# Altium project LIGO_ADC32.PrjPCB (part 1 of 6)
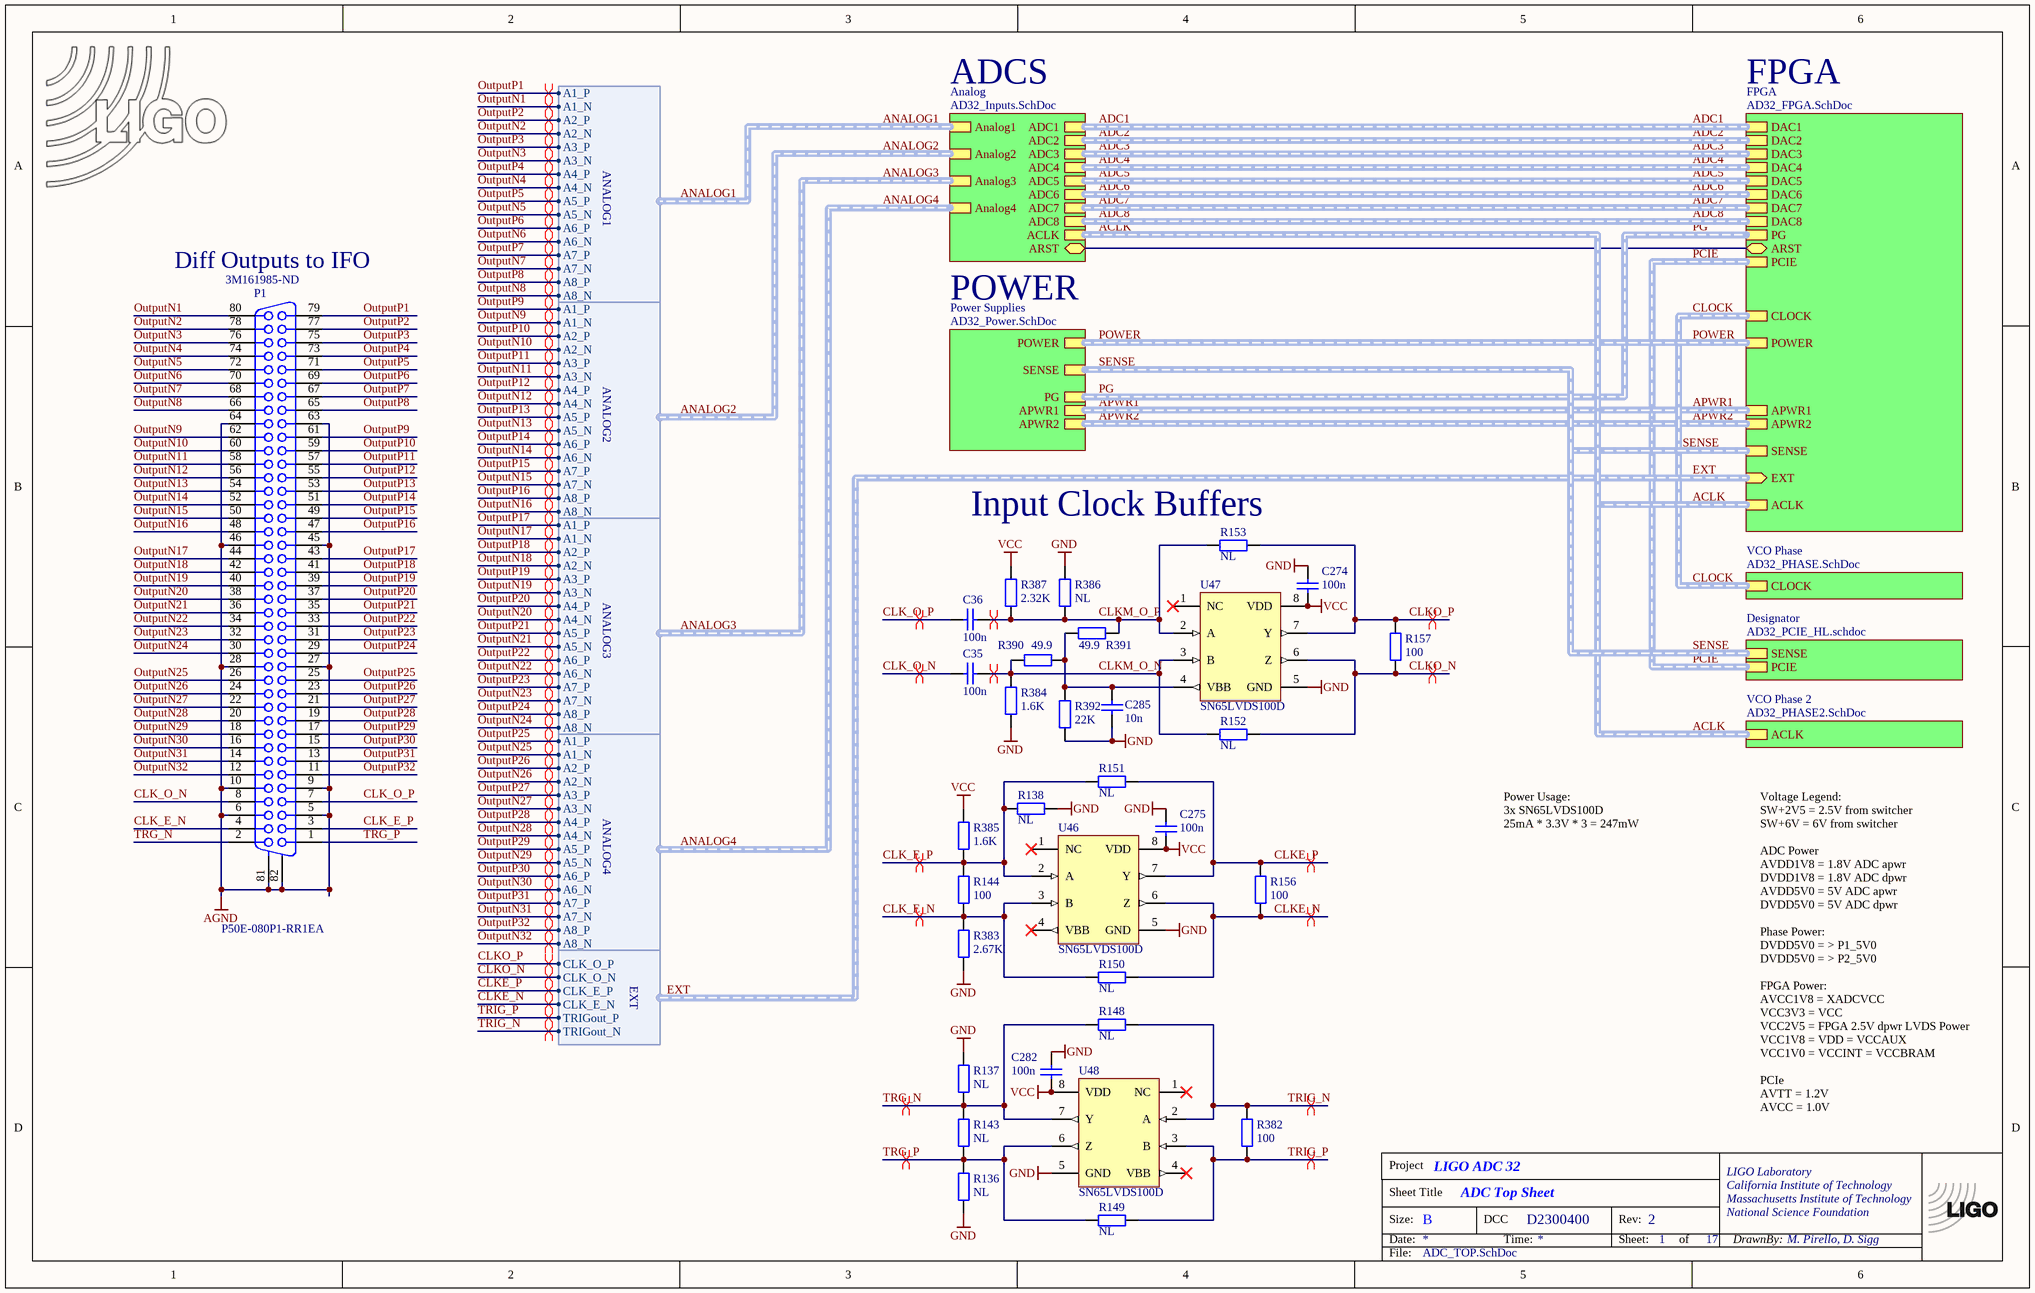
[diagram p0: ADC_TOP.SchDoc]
DCC: D2300400; DCCRevision: 1; ENG: M. Pirello, D. Sigg; Project: LIGO ADC 32; REV: 2; SHEETSIZE: B
17 sheets, 1409 parts. Net scope: hierarchical (ports join the sheet entries above them; power ports are global).
Board file: AD32.PcbDoc
Sheets:
  ADC_TOP.SchDoc
    Analog = AD32_Inputs.SchDoc
      ADC1 = AD32_Conv.SchDoc
        FrontEnd = AdcDaughterFrontEnd.SchDoc
      ADC2 = AD32_Conv.SchDoc
        FrontEnd = AdcDaughterFrontEnd.SchDoc
      ADC3 = AD32_Conv.SchDoc
        FrontEnd = AdcDaughterFrontEnd.SchDoc
      ADC4 = AD32_Conv.SchDoc
        FrontEnd = AdcDaughterFrontEnd.SchDoc
      ADC5 = AD32_Conv.SchDoc
        FrontEnd = AdcDaughterFrontEnd.SchDoc
      ADC6 = AD32_Conv.SchDoc
        FrontEnd = AdcDaughterFrontEnd.SchDoc
      ADC7 = AD32_Conv.SchDoc
        FrontEnd = AdcDaughterFrontEnd.SchDoc
      ADC8 = AD32_Conv.SchDoc
        FrontEnd = AdcDaughterFrontEnd.SchDoc
    FPGA = AD32_FPGA.SchDoc
      FPGA INTERFACE = FPGA_ARTIX7.SchDoc
      ADC = AD32_XADC.SchDoc
      PRG = AD32_FLASH.SchDoc
    VCO Phase = AD32_PHASE.SchDoc
    Designator = AD32_PCIE_HL.SchDoc
      ChassisTimingInterfacePCIE = AD32_PCIE.SchDoc
    Power Supplies = AD32_Power.SchDoc
      Diff Power = AD32_Bipolar1.SchDoc
      Linear Supplies = AD32_Linear1.SchDoc
      Pos Power = AD32_Bipolar2.SchDoc
      PowerFPGA = AD32_PowerFPGA.SchDoc
    VCO Phase 2 = AD32_PHASE2.SchDoc

## Sheet ADC_TOP.SchDoc: ADC Top Sheet
size B; Engineer: Daniel Sigg; Revision: 1; SheetNumber: 1; SheetTotal: 17; PageSetup: Record=PageOptions¦CenterHorizontal=True¦CenterVertical=True¦PrintScale=1.12¦XCorrection=1.00¦YCorrection=1.00¦PrintKind=0¦BorderSize=5000000¦LeftOffset=0¦BottomOffset=0¦Orientation=2¦PaperLength=1000¦PaperWidth=1000¦Scale=100¦PaperSource=7¦PrintQuality=-4¦MediaType=1¦DitherType=10¦PaperKind=Letter¦PrintScaleMode=1

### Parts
(Parts that share a designator on the sheet are numbered #1, #2 ... from top to bottom, then left to right.)
*?#1  TitleBlock  (value not drawn)  (graphical)
C35  100n  [CC1005-0402]
C36  100n  [CC1005-0402]
C274  100n  [CC1005-0402]
C275  100n  [CC1005-0402]
C282  100n  [CC1005-0402]
C285  10n  [CC1005-0402]
LOGO1  LIGO logo  [LIGO-LOGO-SM]  (value not drawn)  (no BOM)
P1  P50E-080P1-RR1EA  Supplier Part Number 1: 3M161985-ND  [P50E-080-SR1]
R136  NL  [CR1005-0402]
R137  NL  [CR1005-0402]
R138  NL  [CR1005-0402]
R143  NL  [CR1005-0402]
R144  100  [CR1005-0402]
R148  NL  [CR1005-0402]
R149  NL  [CR1005-0402]
R150  NL  [CR1005-0402]
R151  NL  [CR1005-0402]
R152  NL  [CR1005-0402]
R153  NL  [CR1005-0402]
R156  100  [CR0603-0201]
R157  100  [CR0603-0201]
R382  100  [CR0603-0201]
R383  2.67K  [CR1005-0402]
R384  1.6K  [CR1005-0402]
R385  1.6K  [CR1005-0402]
R386  NL  [CR1005-0402]
R387  2.32K  [CR1005-0402]
R390  49.9  [CR1005-0402]
R391  49.9  [CR1005-0402]
R392  22K  [CR1005-0402]
U46  SN65LVDS100D  [MSOP8]
U47  SN65LVDS100D  [MSOP8]
U48  SN65LVDS100D  [MSOP8]

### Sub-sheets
Analog = AD32_Inputs.SchDoc: Analog1 (harness ANALOG1), Analog2 (harness ANALOG2), Analog3 (harness ANALOG3), Analog4 (harness ANALOG4), ADC1 (harness DAC1), ADC2 (harness DAC2), ADC3 (harness DAC3), ADC4 (harness DAC4), ADC5 (harness DAC4), ADC6 (harness DAC4), ADC8 (harness DAC4), ADC7 (harness DAC4), ACLK (harness DAC4), ARST (bidir)
Designator = AD32_PCIE_HL.schdoc: PCIE (harness PCIE), SENSE (harness SENSE)
FPGA = AD32_FPGA.SchDoc: DAC4 (harness S1_16), DAC3 (harness S17_32), DAC2 (harness S33_48), DAC7 (harness S49_64), CLOCK (harness CLOCK), PCIE (harness PCIE), POWER (harness POWER), APWR1 (harness CONFIG), APWR2 (harness CONFIG), PG (harness APWR2), SENSE (harness SENSE), EXT (in, harness EXT), DAC5 (harness S49_64), DAC6 (harness S49_64), DAC8 (harness S49_64), DAC1 (harness S49_64), ACLK (harness CLOCK), ARST (bidir)
Power Supplies = AD32_Power.SchDoc: PG (harness APWR2), SENSE (harness SENSE), APWR1 (harness APWR2), APWR2 (harness APWR2), POWER (harness POWER)
VCO Phase = AD32_PHASE.SchDoc: CLOCK (harness CLOCK)
VCO Phase 2 = AD32_PHASE2.SchDoc: ACLK (harness CLOCK)

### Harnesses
EXT: CLK_O_N, CLK_E_P, CLK_E_N, CLK_O_P, TRIGout_P, TRIGout_N
ANALOG1: A1_P, A2_P, A2_N, A1_N, A3_P, A4_P, A4_N, A3_N, A5_P, A6_P, A6_N, A5_N, A7_P, A8_P, A8_N, A7_N
ANALOG2: A1_P, A2_P, A2_N, A1_N, A3_P, A4_P, A4_N, A3_N, A5_P, A6_P, A6_N, A5_N, A7_P, A8_P, A8_N, A7_N
ANALOG3: A1_P, A2_P, A2_N, A1_N, A3_P, A4_P, A4_N, A3_N, A5_P, A6_P, A6_N, A5_N, A7_P, A8_P, A8_N, A7_N
ANALOG4: A1_P, A2_P, A2_N, A1_N, A3_P, A4_P, A4_N, A3_N, A5_P, A6_P, A6_N, A5_N, A7_P, A8_P, A8_N, A7_N

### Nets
AGND: P1.5 P1.6 P1.9 P1.10 P1.27 P1.28 P1.45 P1.46 P1.63 P1.64 P1.81(MH1) P1.82(MH2)
GND: C274.1 C275.1 C282.1 C285.1 R136.2 R137.1 R138.2 R383.2 R384.2 R386.1 R392.2 U46.5(GND) U47.5(GND) U48.5(GND)
VCC: C274.2 C275.2 C282.2 R385.1 R387.1 U46.8(VDD) U47.8(VDD) U48.8(VDD)
ADC.RST: sheet Analog/ARST, sheet FPGA/ARST
CLK_E_N: P1.4 R144.2 R150.1 R383.1 U46.3(B)
CLK_E_P: P1.3 R138.1 R144.1 R151.1 R385.2 U46.2(A)
CLK_O_N: C35.1 P1.8
CLK_O_P: C36.1 P1.7
CLKE_N: R150.2 R156.2 U46.6(Z) ; sheet FPGA/EXT.CLK_E_N
CLKE_P: R151.2 R156.1 U46.7(Y) ; sheet FPGA/EXT.CLK_E_P
CLKM_O_N: C35.2 R152.1 R384.1 R390.2 U47.3(B)
CLKM_O_P: C36.2 R153.1 R386.2 R387.2 R391.1 U47.2(A)
CLKO_N: R152.2 R157.2 U47.6(Z) ; sheet FPGA/EXT.CLK_O_N
CLKO_P: R153.2 R157.1 U47.7(Y) ; sheet FPGA/EXT.CLK_O_P
OutputN1: P1.80 ; sheet Analog/Analog1.A1_N  [project net ANALOG1.A1_N]
OutputN2: P1.78 ; sheet Analog/Analog1.A2_N  [project net ANALOG1.A2_N]
OutputN3: P1.76 ; sheet Analog/Analog1.A3_N  [project net ANALOG1.A3_N]
OutputN4: P1.74 ; sheet Analog/Analog1.A4_N  [project net ANALOG1.A4_N]
OutputN5: P1.72 ; sheet Analog/Analog1.A5_N  [project net ANALOG1.A5_N]
OutputN6: P1.70 ; sheet Analog/Analog1.A6_N  [project net ANALOG1.A6_N]
OutputN7: P1.68 ; sheet Analog/Analog1.A7_N  [project net ANALOG1.A7_N]
OutputN8: P1.66 ; sheet Analog/Analog1.A8_N  [project net ANALOG1.A8_N]
OutputN9: P1.62 ; sheet Analog/Analog2.A1_N  [project net ANALOG2.A1_N]
OutputN10: P1.60 ; sheet Analog/Analog2.A2_N  [project net ANALOG2.A2_N]
OutputN11: P1.58 ; sheet Analog/Analog2.A3_N  [project net ANALOG2.A3_N]
OutputN12: P1.56 ; sheet Analog/Analog2.A4_N  [project net ANALOG2.A4_N]
OutputN13: P1.54 ; sheet Analog/Analog2.A5_N  [project net ANALOG2.A5_N]
OutputN14: P1.52 ; sheet Analog/Analog2.A6_N  [project net ANALOG2.A6_N]
OutputN15: P1.50 ; sheet Analog/Analog2.A7_N  [project net ANALOG2.A7_N]
OutputN16: P1.48 ; sheet Analog/Analog2.A8_N  [project net ANALOG2.A8_N]
OutputN17: P1.44 ; sheet Analog/Analog3.A1_N  [project net ANALOG3.A1_N]
OutputN18: P1.42 ; sheet Analog/Analog3.A2_N  [project net ANALOG3.A2_N]
OutputN19: P1.40 ; sheet Analog/Analog3.A3_N  [project net ANALOG3.A3_N]
OutputN20: P1.38 ; sheet Analog/Analog3.A4_N  [project net ANALOG3.A4_N]
OutputN21: P1.36 ; sheet Analog/Analog3.A5_N  [project net ANALOG3.A5_N]
OutputN22: P1.34 ; sheet Analog/Analog3.A6_N  [project net ANALOG3.A6_N]
OutputN23: P1.32 ; sheet Analog/Analog3.A7_N  [project net ANALOG3.A7_N]
OutputN24: P1.30 ; sheet Analog/Analog3.A8_N  [project net ANALOG3.A8_N]
OutputN25: P1.26 ; sheet Analog/Analog4.A1_N  [project net ANALOG4.A1_N]
OutputN26: P1.24 ; sheet Analog/Analog4.A2_N  [project net ANALOG4.A2_N]
OutputN27: P1.22 ; sheet Analog/Analog4.A3_N  [project net ANALOG4.A3_N]
OutputN28: P1.20 ; sheet Analog/Analog4.A4_N  [project net ANALOG4.A4_N]
OutputN29: P1.18 ; sheet Analog/Analog4.A5_N  [project net ANALOG4.A5_N]
OutputN30: P1.16 ; sheet Analog/Analog4.A6_N  [project net ANALOG4.A6_N]
OutputN31: P1.14 ; sheet Analog/Analog4.A7_N  [project net ANALOG4.A7_N]
OutputN32: P1.12 ; sheet Analog/Analog4.A8_N  [project net ANALOG4.A8_N]
OutputP1: P1.79 ; sheet Analog/Analog1.A1_P  [project net ANALOG1.A1_P]
OutputP2: P1.77 ; sheet Analog/Analog1.A2_P  [project net ANALOG1.A2_P]
OutputP3: P1.75 ; sheet Analog/Analog1.A3_P  [project net ANALOG1.A3_P]
OutputP4: P1.73 ; sheet Analog/Analog1.A4_P  [project net ANALOG1.A4_P]
OutputP5: P1.71 ; sheet Analog/Analog1.A5_P  [project net ANALOG1.A5_P]
OutputP6: P1.69 ; sheet Analog/Analog1.A6_P  [project net ANALOG1.A6_P]
OutputP7: P1.67 ; sheet Analog/Analog1.A7_P  [project net ANALOG1.A7_P]
OutputP8: P1.65 ; sheet Analog/Analog1.A8_P  [project net ANALOG1.A8_P]
OutputP9: P1.61 ; sheet Analog/Analog2.A1_P  [project net ANALOG2.A1_P]
OutputP10: P1.59 ; sheet Analog/Analog2.A2_P  [project net ANALOG2.A2_P]
OutputP11: P1.57 ; sheet Analog/Analog2.A3_P  [project net ANALOG2.A3_P]
OutputP12: P1.55 ; sheet Analog/Analog2.A4_P  [project net ANALOG2.A4_P]
OutputP13: P1.53 ; sheet Analog/Analog2.A5_P  [project net ANALOG2.A5_P]
OutputP14: P1.51 ; sheet Analog/Analog2.A6_P  [project net ANALOG2.A6_P]
OutputP15: P1.49 ; sheet Analog/Analog2.A7_P  [project net ANALOG2.A7_P]
OutputP16: P1.47 ; sheet Analog/Analog2.A8_P  [project net ANALOG2.A8_P]
OutputP17: P1.43 ; sheet Analog/Analog3.A1_P  [project net ANALOG3.A1_P]
OutputP18: P1.41 ; sheet Analog/Analog3.A2_P  [project net ANALOG3.A2_P]
OutputP19: P1.39 ; sheet Analog/Analog3.A3_P  [project net ANALOG3.A3_P]
OutputP20: P1.37 ; sheet Analog/Analog3.A4_P  [project net ANALOG3.A4_P]
OutputP21: P1.35 ; sheet Analog/Analog3.A5_P  [project net ANALOG3.A5_P]
OutputP22: P1.33 ; sheet Analog/Analog3.A6_P  [project net ANALOG3.A6_P]
OutputP23: P1.31 ; sheet Analog/Analog3.A7_P  [project net ANALOG3.A7_P]
OutputP24: P1.29 ; sheet Analog/Analog3.A8_P  [project net ANALOG3.A8_P]
OutputP25: P1.25 ; sheet Analog/Analog4.A1_P  [project net ANALOG4.A1_P]
OutputP26: P1.23 ; sheet Analog/Analog4.A2_P  [project net ANALOG4.A2_P]
OutputP27: P1.21 ; sheet Analog/Analog4.A3_P  [project net ANALOG4.A3_P]
OutputP28: P1.19 ; sheet Analog/Analog4.A4_P  [project net ANALOG4.A4_P]
OutputP29: P1.17 ; sheet Analog/Analog4.A5_P  [project net ANALOG4.A5_P]
OutputP30: P1.15 ; sheet Analog/Analog4.A6_P  [project net ANALOG4.A6_P]
OutputP31: P1.13 ; sheet Analog/Analog4.A7_P  [project net ANALOG4.A7_P]
OutputP32: P1.11 ; sheet Analog/Analog4.A8_P  [project net ANALOG4.A8_P]
TRG_N: P1.2 R137.2 R143.1 R148.2 U48.7(Y)
TRG_P: P1.1 R136.1 R143.2 R149.2 U48.6(Z)
TRIG_N: R148.1 R382.1 U48.2(A) ; sheet FPGA/EXT.TRIGout_N  [project net EXT.TRIGout_N]
TRIG_P: R149.1 R382.2 U48.3(B) ; sheet FPGA/EXT.TRIGout_P  [project net EXT.TRIGout_P]
NetC285_2: C285.2 R390.1 R391.2 R392.1 U47.4(VBB)

Not connected (* = marked no-connect by the designer): U46 1(NC)* 4(VBB)*; U47 1(NC)*; U48 1(NC)* 4(VBB)*

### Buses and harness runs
harness ACLK = sheet Analog/ACLK = sheet FPGA/ACLK = sheet VCO Phase 2/ACLK
harness ADC1 = sheet Analog/ADC1 = sheet FPGA/DAC1
harness ADC2 = sheet Analog/ADC2 = sheet FPGA/DAC2
harness ADC3 = sheet Analog/ADC3 = sheet FPGA/DAC3
harness ADC4 = sheet Analog/ADC4 = sheet FPGA/DAC4
harness ADC5 = sheet Analog/ADC5 = sheet FPGA/DAC5
harness ADC6 = sheet Analog/ADC6 = sheet FPGA/DAC6
harness ADC7 = sheet Analog/ADC7 = sheet FPGA/DAC7
harness ADC8 = sheet Analog/ADC8 = sheet FPGA/DAC8
harness ANALOG1 = sheet Analog/Analog1
harness ANALOG2 = sheet Analog/Analog2
harness ANALOG3 = sheet Analog/Analog3
harness ANALOG4 = sheet Analog/Analog4
harness APWR1 = sheet FPGA/APWR1 = sheet Power Supplies/APWR1
harness APWR2 = sheet FPGA/APWR2 = sheet Power Supplies/APWR2
harness CLOCK = sheet FPGA/CLOCK = sheet VCO Phase/CLOCK
harness EXT = sheet FPGA/EXT
harness PCIE = sheet Designator/PCIE = sheet FPGA/PCIE
harness PG = sheet FPGA/PG = sheet Power Supplies/PG
harness POWER = sheet FPGA/POWER = sheet Power Supplies/POWER
harness SENSE = sheet Designator/SENSE = sheet FPGA/SENSE = sheet Power Supplies/SENSE

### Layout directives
differential pair: ANALOG1.A1_N, ANALOG1.A1_P, ANALOG1.A2_N, ANALOG1.A2_P, ANALOG1.A3_N, ANALOG1.A3_P, ANALOG1.A4_N, ANALOG1.A4_P, ANALOG1.A5_N, ANALOG1.A5_P, ANALOG1.A6_N, ANALOG1.A6_P, ANALOG1.A7_N, ANALOG1.A7_P, ANALOG1.A8_N, ANALOG1.A8_P, ANALOG2.A1_N, ANALOG2.A1_P, ANALOG2.A2_N, ANALOG2.A2_P, ANALOG2.A3_N, ANALOG2.A3_P, ANALOG2.A4_N, ANALOG2.A4_P, ANALOG2.A5_N, ANALOG2.A5_P, ANALOG2.A6_N, ANALOG2.A6_P, ANALOG2.A7_N, ANALOG2.A7_P, ANALOG2.A8_N, ANALOG2.A8_P, ANALOG3.A1_N, ANALOG3.A1_P, ANALOG3.A2_N, ANALOG3.A2_P, ANALOG3.A3_N, ANALOG3.A3_P, ANALOG3.A4_N, ANALOG3.A4_P, ANALOG3.A5_N, ANALOG3.A5_P, ANALOG3.A6_N, ANALOG3.A6_P, ANALOG3.A7_N, ANALOG3.A7_P, ANALOG3.A8_N, ANALOG3.A8_P, ANALOG4.A1_N, ANALOG4.A1_P, ANALOG4.A2_N, ANALOG4.A2_P, ANALOG4.A3_N, ANALOG4.A3_P, ANALOG4.A4_N, ANALOG4.A4_P, ANALOG4.A5_N, ANALOG4.A5_P, ANALOG4.A6_N, ANALOG4.A6_P, ANALOG4.A7_N, ANALOG4.A7_P, ANALOG4.A8_N, ANALOG4.A8_P, CLKE_N, CLKE_P, CLKM_O_N, CLKM_O_P, CLKO_N, CLKO_P, EXT.TRIGout_N, EXT.TRIGout_P
differential pair; differential pair class PCIe Clocks: CLK_E_N, CLK_E_P, CLK_O_N, CLK_O_P, TRG_N, TRG_P

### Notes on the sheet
- ADCS
- FPGA
- (near P1) Diff Outputs to IFO
- POWER
- (near R153) Input Clock Buffers
- Power Usage:
  3x SN65LVDS100D
  25mA * 3.3V * 3 = 247mW
- Voltage Legend:
  SW+2V5 = 2.5V from switcher
  SW+6V = 6V from switcher
  ADC Power
  AVDD1V8 = 1.8V ADC apwr
  DVDD1V8 = 1.8V ADC dpwr
  AVDD5V0 = 5V ADC apwr
  DVDD5V0 = 5V ADC dpwr
  Phase Power:
  DVDD5V0 = > P1_5V0
  DVDD5V0 = > P2_5V0
  FPGA Power:
  AVCC1V8 = XADCVCC
  VCC3V3 = VCC
  VCC2V5 = FPGA 2.5V dpwr LVDS Power
  VCC1V8 = VDD = VCCAUX
  VCC1V0 = VCCINT = VCCBRAM
  PCIe
  AVTT = 1.2V
  AVCC = 1.0V

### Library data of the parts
C35 C36 C274 C275 C282 = ChipCap: C0402 100n; Part Number: CL05B104KA5NNNC
C285 = ChipCap: C0402 10n; Part Number: CC0402KRX7R9BB103
LOGO1 = LIGO_logo: NL
P1 = PE50E-080 Connector: 3M Pak 50 plug connector; Part Number: P50E-080P1-RR1-EA
R136-R138 R143 R148-R153 R386 = ChipRes1: R0402 NL
R144 = ChipRes1: R0402 100; Part Number: TNPW0402100RBEED
R156 R157 R382 = ChipRes1: R0201 100; Part Number: ERA-1AEB101C
R383 = ChipRes1: R0402 2.67k; Part Number: RT0402BRD072K67L
R384 R385 = ChipRes1: R0402 1.6k; Part Number: ERA-2AEB162X
R387 = ChipRes1: R0402 2.32k; Part Number: RT0402BRD072K32L
R390 R391 = ChipRes1: R0402 49.9; Part Number: ERA-2AEB49R9X
R392 = ChipRes1: R0402 22k; Part Number: ERA-2AED223X
U46-U48 = SN65LVDS100: DIFF TRANSLATOR; Part Number: 296-39184-1-ND

## Sheet AD32_Inputs.SchDoc: Converter Prototype Analog Inputs
size B; Engineer: Daniel Sigg; Revision: 1; SheetNumber: 4; SheetTotal: 17; SPICEModelCache: <root> / <DocumentId>USFJKJMQ</DocumentId> / <CacheFrame Number="0"> / <Model Name="op284f" Kind="CKT"> / <Text>* OP284F SPICE Macro-model              11/95 / Rev. B / *                                       ARG / ADSC / * / * Revision History: / * / *     Rev. B / * Changed the short-circuit output current limit from +/- 7.5mA / * to +/- 6.5mA to reflect final data sheet limits. / * / * Changed Vos spec to conform to final data sheet value of / * 125uV, up from 50uV. / * / * / * This version of the OP284 model simulates the worst-case / * parameters of the 'F' grade.  The worst-case parameters / * used correspond to those in the data sheet. / * / * Copyright 1993 by Analog Devices / * / * Refer to "README.DOC" file for License Statement. Use of this model / * indicates your acceptance of the terms and provisions in the License / * Statement. / * / * Node assignments / *                non-inverting input / *                ¦   inverting input / *                ¦   ¦   positive supply / *                ¦   ¦   ¦   negative supply / *                ¦   ¦   ¦   ¦   output / *                ¦   ¦   ¦   ¦   ¦ / .SUBCKT OP284F   1   2   99  50  45 / * / * INPUT STAGE / * / Q1   5    2    3    QIN 1 / Q2   6    11   3    QIN 1 / Q3   7    2    4    QIP 1 / Q4   8    11   4    QIP 1 / DC1  2    11   DC / DC2  11   2    DC / Q5   4    9    99   QIP 1 / Q6   9    9    99   QIP 1 / Q7   3    10   50   QIN 1 / Q8   10   10   50   QIN 1 / R1   99   5    4E3 / R2   99   6    4E3 / R3   7    50   4E3 / R4   8    50   4E3 / IREF 9    10   50.5E-6 / EOS  1    11   POLY(2) (22,98) (14,98) -125E-6 501.2E-3 1 / IOS  2    1    25E-9 / CIN  1    2    2E-12 / GN1  98   1    17 98 1E-3 / GN2  98   2    23 98 1E-3 / * / * VOLTAGE NOISE SOURCE WITH FLICKER NOISE / * / VN1  13   98   DC 2 / VN2  98   15   DC 2 / DN1  13   14   DEN / DN2  14   15   DEN / * / * CURRENT NOISE SOURCE WITH FLICKER NOISE / * / VN3  16   98   DC 2 / VN4  98   18   DC 2 / DN3  16   17   DIN / DN4  17   18   DIN / * / * 2ND CURRENT NOISE SOURCE WITH FLICKER NOISE / * / VN5  19   98   DC 2 / VN6  98   24   DC 2 / DN5  19   23   DIN / DN6  23   24   DIN / * / * GAIN STAGE / * / EREF 98   0    POLY(2) (99,0) (50,0) 0 0.5 0.5 / G1   98   20   POLY(2) (6,5) (8,7) 0 0.5E-3 0.5E-3 / R9   20   98   1E3 / * / * COMMON MODE STAGE WITH ZERO AT 5KHZ / * / ECM  98   21   POLY(2) (1,98) (2,98) 0 0.5 0.5 / R10  21   22   1 / R11  22   98   100E-6 / C4   21   22   31.756E-6 / * / * NEGATIVE ZERO AT 20MHZ / * / E1   27   98   20 98 1 / R17  27   28   1 / R18  28   98   1E-6 / C8   25   26   7.958E-9 / ENZ  25   98   27 28 1 / VNZ  26   98   DC 0 / FNZ  27   28   VNZ -1 / * / * POLE AT 40MHZ / * / G4   98   29   28 98 1E6 / R19  29   98   1 / C9   29   98   3.979E-9 / * / * POLE AT 40MHZ / * / G5   98   30   29 98 1 / R20  30   98   1 / C10  30   98   3.979E-9 / * / * OUTUT STAGE / * / ISY  99   50   0.526E-3 / GIN  50   31   POLY(1) (30,98) 0.862574E-6 511.855E-6 / RIN  31   50   2.75E6 / VB   99   32   0.7 / Q11  32   31   33   QON 1 / R21  33   34   4.5E3 / I1   34   50   50E-6 / R22  99   35   6E3 / Q12  36   36   35   QOP 1 / I2   36   50   50E-6 / R23  99   37   2.6E3 / R24  34   38   5E3 / Q13  39   36   37   QOP 1 / Q14  39   38   40   QON 1.5 / R25  40   50   40 / Q15  39   39   41   QON 1 / R26  41   42   1E3 / R27  99   43   220 / Q16  44   44   43   QOP 1.5 / Q17  44   39   42   QON 1 / R28  42   50   2E3 / VSCP 99   97   DC 0 / FSCP 46   99   VSCP 1 / RSCP 46   99   125 / Q20  44   46   99   QOP 1 / Q18  45   44   97   QOP 4.5 / Q19  45   34   51   QON 4.5 / VSCN 51   50   DC 0 / FSCN 50   47   VSCN 1 / RSCN 47   50   122 / Q21  34   47   50   QON 1 / CC2  31   45   20E-12 / CF1  31   34   15E-12 / CF2  31   42   15E-12 / CO1  34   45   15E-12 / CO2  42   45   5E-12 / D3   45   99   DX / D4   50   45   DX / .MODEL DC D(IS=130E-21) / .MODEL DX D() / .MODEL DEN D(RS=100 KF=12E-15 AF=1) / .MODEL DIN D(RS=5.358 KF=56E-15 AF=1) / .MODEL QIN NPN(BF=250 VA=200 IS=0.5E-16) / .MODEL QIP PNP(BF=60 VA=100 IS=0.5E-16) / .MODEL QON NPN(BF=200 VA=200 IS=0.5E-16 RC=140) / .MODEL QOP PNP(BF=200 VA=200 IS=0.5E-16 RC=210) / .ENDS</Text> / </Model> / </CacheFrame> / </root>
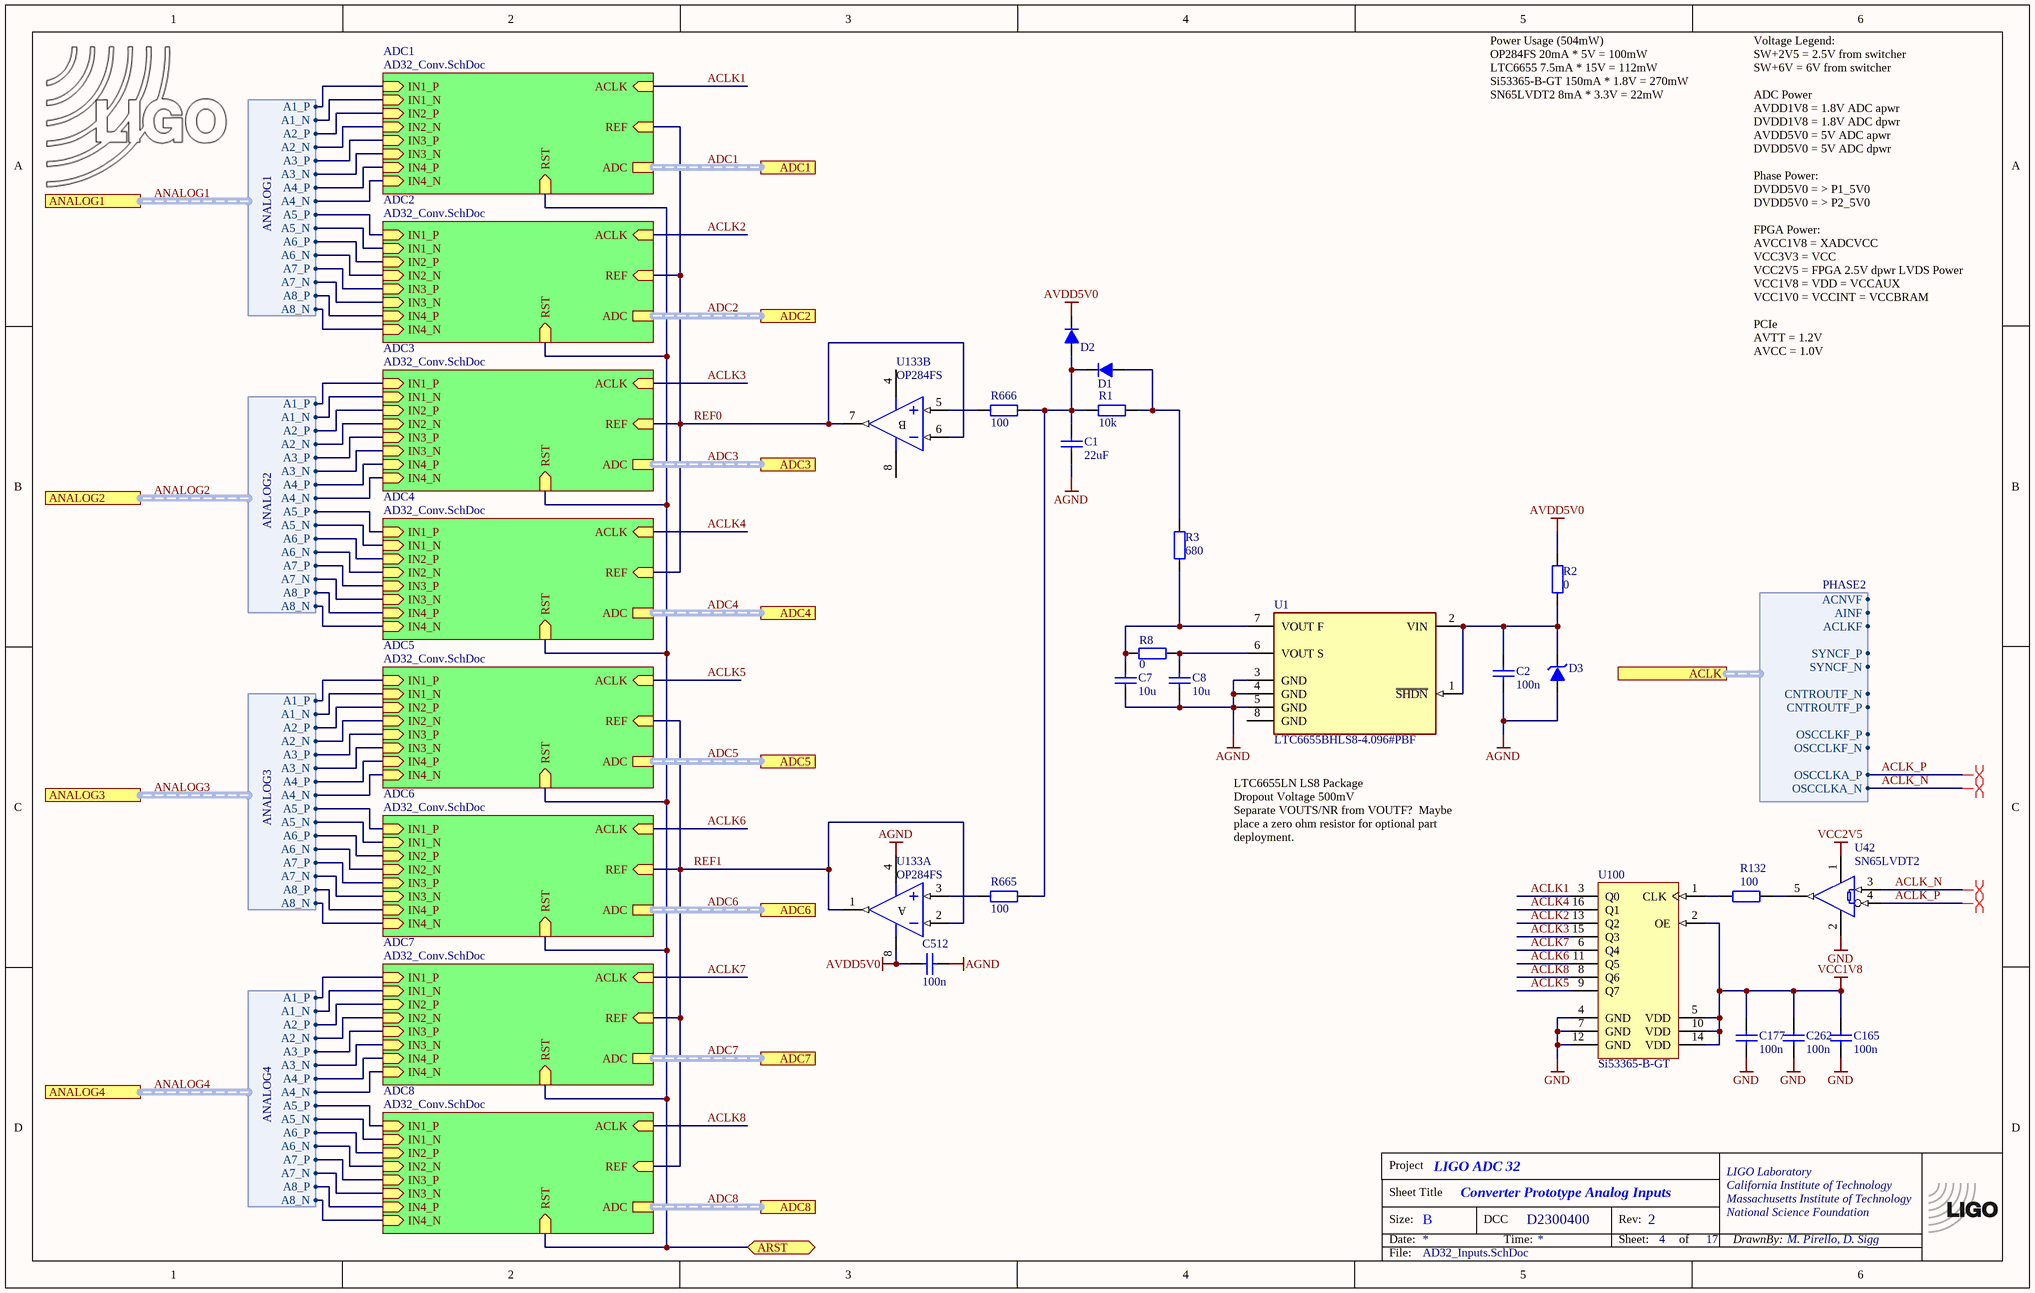
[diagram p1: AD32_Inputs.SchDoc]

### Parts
(Parts that share a designator on the sheet are numbered #1, #2 ... from top to bottom, then left to right.)
*?#2  TitleBlock  (value not drawn)  (graphical)
C1  22uF  [CC5650-2220]
C2  100n  [CC2013-0805]
C7  10u  [CC3225-1210]
C8  10u  [CC3225-1210]
C165  100n  [CC2013-0805]
C177  100n  [CC2013-0805]
C262  100n  [CC2013-0805]
C512  100n  [CC2013-0805]
D1  DIODE  [DO-SOD123]  (value not drawn)
D2  DIODE  [DO-SOD123]  (value not drawn)
D3  NS  [DO-SOD123]  (value not drawn)
LOGO?#1  LIGO logo  [LIGO_LOGO]  (value not drawn)  (graphical)
R1  10k  [CR1608-0603]
R2  0  [CR1608-0603]
R3  680  [CR1608-0603]
R8  0  [CR1608-0603]
R132  100  [CR1005-0402]
R665  100  [CR1608-0603]
R666  100  [CR1608-0603]
U1  LTC6655BHLS8-4.096#PBF  [FP-LS8-8-05-08-1852-MFG]
U42  SN65LVDT2  [SO-G5/E2.4]
U100  Si53365-B-GT  [SLAB-TSSOP-16_L]
U133  OP284FS  [SO-8_N]  (parts A,B of 2)

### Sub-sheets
ADC1 = AD32_Conv.SchDoc: REF (in), IN1_P (in), IN1_N (in), IN2_P (in), IN2_N (in), IN3_P (in), IN3_N (in), IN4_P (in), IN4_N (in), ACLK (in), ADC (harness ADC), RST (in)
ADC2 = AD32_Conv.SchDoc: REF (in), IN1_P (in), IN1_N (in), IN2_P (in), IN2_N (in), IN3_P (in), IN3_N (in), IN4_P (in), IN4_N (in), ACLK (in), ADC (harness ADC), RST (in)
ADC3 = AD32_Conv.SchDoc: REF (in), IN1_P (in), IN1_N (in), IN2_P (in), IN2_N (in), IN3_P (in), IN3_N (in), IN4_P (in), IN4_N (in), ADC (harness ADC), ACLK (in), RST (in)
ADC4 = AD32_Conv.SchDoc: REF (in), IN1_P (in), IN1_N (in), IN2_P (in), IN2_N (in), IN3_P (in), IN3_N (in), IN4_P (in), IN4_N (in), ADC (harness ADC), ACLK (in), RST (in)
ADC5 = AD32_Conv.SchDoc: REF (in), IN1_P (in), IN1_N (in), IN2_P (in), IN2_N (in), IN3_P (in), IN3_N (in), IN4_P (in), IN4_N (in), ADC (harness ADC), ACLK (in), RST (in)
ADC6 = AD32_Conv.SchDoc: REF (in), IN1_P (in), IN1_N (in), IN2_P (in), IN2_N (in), IN3_P (in), IN3_N (in), IN4_P (in), IN4_N (in), ADC (harness ADC), ACLK (in), RST (in)
ADC7 = AD32_Conv.SchDoc: REF (in), IN1_P (in), IN1_N (in), IN2_P (in), IN2_N (in), IN3_P (in), IN3_N (in), IN4_P (in), IN4_N (in), ADC (harness ADC), ACLK (in), RST (in)
ADC8 = AD32_Conv.SchDoc: REF (in), IN1_P (in), IN1_N (in), IN2_P (in), IN2_N (in), IN3_P (in), IN3_N (in), IN4_P (in), IN4_N (in), ADC (harness ADC), ACLK (in), RST (in)

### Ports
ACLK (harness PHASE2), ADC1 (harness ADC), ADC2 (harness ADC), ADC3 (harness ADC), ADC4 (harness ADC), ADC5 (harness ADC), ADC6 (harness ADC), ADC7 (harness ADC), ADC8 (harness ADC), ANALOG1 (harness ANALOG1), ANALOG2 (harness ANALOG2), ANALOG3 (harness ANALOG3), ANALOG4 (harness ANALOG4), ARST (bidir)

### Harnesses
ANALOG4: A1_P, A2_P, A2_N, A1_N, A3_P, A4_P, A4_N, A3_N, A5_P, A6_P, A6_N, A5_N, A7_P, A8_P, A8_N, A7_N
ANALOG3: A1_P, A2_P, A2_N, A1_N, A3_P, A4_P, A4_N, A3_N, A5_P, A6_P, A6_N, A5_N, A7_P, A8_P, A8_N, A7_N
ANALOG2: A1_P, A2_P, A2_N, A1_N, A3_P, A4_P, A4_N, A3_N, A5_P, A6_P, A6_N, A5_N, A7_P, A8_P, A8_N, A7_N
ANALOG1: A1_P, A2_P, A2_N, A1_N, A3_P, A4_P, A4_N, A3_N, A5_P, A6_P, A6_N, A5_N, A7_P, A8_P, A8_N, A7_N
PHASE2: OSCCLKA_N, OSCCLKA_P, CNTROUTF_N, CNTROUTF_P, SYNCF_N, SYNCF_P, ACLKF, ACNVF, AINF, OSCCLKF_P, OSCCLKF_N

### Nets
AGND: C1.1 C2.1 C7.2 C8.2 C512.2 D3.1(A) U1.3(GND) U1.4(GND) U1.5(GND) U133.4(V-)
AVDD5V0: C512.1 D2.2(K) R2.2 U133.8(V+)
GND: C165.2 C177.2 C262.2 U42.2(GND) U100.4(GND) U100.7(GND) U100.12(GND)
VCC1V8: C165.1 C177.1 C262.1 U100.2(OE) U100.5(VDD) U100.10(VDD) U100.14(VDD)
VCC2V5: U42.1(VCC)
ACLK1: U100.3(Q0) ; sheet ADC1/ACLK
ACLK2: U100.13(Q2) ; sheet ADC2/ACLK
ACLK3: U100.15(Q3) ; sheet ADC3/ACLK
ACLK4: U100.16(Q1) ; sheet ADC4/ACLK
ACLK5: U100.9(Q7) ; sheet ADC5/ACLK
ACLK6: U100.11(Q5) ; sheet ADC6/ACLK
ACLK7: U100.6(Q4) ; sheet ADC7/ACLK
ACLK8: U100.8(Q6) ; sheet ADC8/ACLK
ACLK_N: U42.3(A) ; port ACLK.OSCCLKA_N  [project net ACLK.OSCCLKA_N]
ACLK_P: U42.4(B) ; port ACLK.OSCCLKA_P  [project net ACLK.OSCCLKA_P]
ADC.RST: port ARST, sheet ADC1/RST, sheet ADC2/RST, sheet ADC3/RST, sheet ADC4/RST, sheet ADC5/RST, sheet ADC6/RST, sheet ADC7/RST, sheet ADC8/RST
ANALOG1.A1_N: sheet ADC1/IN1_N, port ANALOG1.A1_N
ANALOG1.A1_P: sheet ADC1/IN1_P, port ANALOG1.A1_P
ANALOG1.A2_N: sheet ADC1/IN2_N, port ANALOG1.A2_N
ANALOG1.A2_P: sheet ADC1/IN2_P, port ANALOG1.A2_P
ANALOG1.A3_N: sheet ADC1/IN3_N, port ANALOG1.A3_N
ANALOG1.A3_P: sheet ADC1/IN3_P, port ANALOG1.A3_P
ANALOG1.A4_N: sheet ADC1/IN4_N, port ANALOG1.A4_N
ANALOG1.A4_P: sheet ADC1/IN4_P, port ANALOG1.A4_P
ANALOG1.A5_N: sheet ADC2/IN1_N, port ANALOG1.A5_N
ANALOG1.A5_P: sheet ADC2/IN1_P, port ANALOG1.A5_P
ANALOG1.A6_N: sheet ADC2/IN2_N, port ANALOG1.A6_N
ANALOG1.A6_P: sheet ADC2/IN2_P, port ANALOG1.A6_P
ANALOG1.A7_N: sheet ADC2/IN3_N, port ANALOG1.A7_N
ANALOG1.A7_P: sheet ADC2/IN3_P, port ANALOG1.A7_P
ANALOG1.A8_N: sheet ADC2/IN4_N, port ANALOG1.A8_N
ANALOG1.A8_P: sheet ADC2/IN4_P, port ANALOG1.A8_P
ANALOG2.A1_N: sheet ADC3/IN1_N, port ANALOG2.A1_N
ANALOG2.A1_P: sheet ADC3/IN1_P, port ANALOG2.A1_P
ANALOG2.A2_N: sheet ADC3/IN2_N, port ANALOG2.A2_N
ANALOG2.A2_P: sheet ADC3/IN2_P, port ANALOG2.A2_P
ANALOG2.A3_N: sheet ADC3/IN3_N, port ANALOG2.A3_N
ANALOG2.A3_P: sheet ADC3/IN3_P, port ANALOG2.A3_P
ANALOG2.A4_N: sheet ADC3/IN4_N, port ANALOG2.A4_N
ANALOG2.A4_P: sheet ADC3/IN4_P, port ANALOG2.A4_P
ANALOG2.A5_N: sheet ADC4/IN1_N, port ANALOG2.A5_N
ANALOG2.A5_P: sheet ADC4/IN1_P, port ANALOG2.A5_P
ANALOG2.A6_N: sheet ADC4/IN2_N, port ANALOG2.A6_N
ANALOG2.A6_P: sheet ADC4/IN2_P, port ANALOG2.A6_P
ANALOG2.A7_N: sheet ADC4/IN3_N, port ANALOG2.A7_N
ANALOG2.A7_P: sheet ADC4/IN3_P, port ANALOG2.A7_P
ANALOG2.A8_N: sheet ADC4/IN4_N, port ANALOG2.A8_N
ANALOG2.A8_P: sheet ADC4/IN4_P, port ANALOG2.A8_P
ANALOG3.A1_N: sheet ADC5/IN1_N, port ANALOG3.A1_N
ANALOG3.A1_P: sheet ADC5/IN1_P, port ANALOG3.A1_P
ANALOG3.A2_N: sheet ADC5/IN2_N, port ANALOG3.A2_N
ANALOG3.A2_P: sheet ADC5/IN2_P, port ANALOG3.A2_P
ANALOG3.A3_N: sheet ADC5/IN3_N, port ANALOG3.A3_N
ANALOG3.A3_P: sheet ADC5/IN3_P, port ANALOG3.A3_P
ANALOG3.A4_N: sheet ADC5/IN4_N, port ANALOG3.A4_N
ANALOG3.A4_P: sheet ADC5/IN4_P, port ANALOG3.A4_P
ANALOG3.A5_N: sheet ADC6/IN1_N, port ANALOG3.A5_N
ANALOG3.A5_P: sheet ADC6/IN1_P, port ANALOG3.A5_P
ANALOG3.A6_N: sheet ADC6/IN2_N, port ANALOG3.A6_N
ANALOG3.A6_P: sheet ADC6/IN2_P, port ANALOG3.A6_P
ANALOG3.A7_N: sheet ADC6/IN3_N, port ANALOG3.A7_N
ANALOG3.A7_P: sheet ADC6/IN3_P, port ANALOG3.A7_P
ANALOG3.A8_N: sheet ADC6/IN4_N, port ANALOG3.A8_N
ANALOG3.A8_P: sheet ADC6/IN4_P, port ANALOG3.A8_P
ANALOG4.A1_N: sheet ADC7/IN1_N, port ANALOG4.A1_N
ANALOG4.A1_P: sheet ADC7/IN1_P, port ANALOG4.A1_P
ANALOG4.A2_N: sheet ADC7/IN2_N, port ANALOG4.A2_N
ANALOG4.A2_P: sheet ADC7/IN2_P, port ANALOG4.A2_P
ANALOG4.A3_N: sheet ADC7/IN3_N, port ANALOG4.A3_N
ANALOG4.A3_P: sheet ADC7/IN3_P, port ANALOG4.A3_P
ANALOG4.A4_N: sheet ADC7/IN4_N, port ANALOG4.A4_N
ANALOG4.A4_P: sheet ADC7/IN4_P, port ANALOG4.A4_P
ANALOG4.A5_N: sheet ADC8/IN1_N, port ANALOG4.A5_N
ANALOG4.A5_P: sheet ADC8/IN1_P, port ANALOG4.A5_P
ANALOG4.A6_N: sheet ADC8/IN2_N, port ANALOG4.A6_N
ANALOG4.A6_P: sheet ADC8/IN2_P, port ANALOG4.A6_P
ANALOG4.A7_N: sheet ADC8/IN3_N, port ANALOG4.A7_N
ANALOG4.A7_P: sheet ADC8/IN3_P, port ANALOG4.A7_P
ANALOG4.A8_N: sheet ADC8/IN4_N, port ANALOG4.A8_N
ANALOG4.A8_P: sheet ADC8/IN4_P, port ANALOG4.A8_P
REF0: U133.6(IN-) U133.7(OUT) ; sheet ADC1/REF, sheet ADC2/REF, sheet ADC3/REF, sheet ADC4/REF
REF1: U133.1(OUT) U133.2(IN-) ; sheet ADC5/REF, sheet ADC6/REF, sheet ADC7/REF, sheet ADC8/REF
NetC1_2: C1.2 D1.2(K) D2.1(A) R1.1 R665.2 R666.2
NetC2_2: C2.2 D3.2(K) R2.1 U1.1(~{SHDN}) U1.2(VIN)
NetC7_1: C7.1 R3.2 R8.2 U1.7(VOUT_F)
NetC8_1: C8.1 R8.1 U1.6(VOUT_S)
NetD1_1: D1.1(A) R1.2 R3.1
NetR132_1: R132.1 U100.1(CLK)
NetR132_2: R132.2 U42.5(R)
NetR665_1: R665.1 U133.3(IN+)
NetR666_1: R666.1 U133.5(IN+)

Not connected (* = marked no-connect by the designer): U1 8(GND)

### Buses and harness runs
harness ADC1 = port ADC1 = sheet ADC1/ADC
harness ADC2 = port ADC2 = sheet ADC2/ADC
harness ADC3 = port ADC3 = sheet ADC3/ADC
harness ADC4 = port ADC4 = sheet ADC4/ADC
harness ADC5 = port ADC5 = sheet ADC5/ADC
harness ADC6 = port ADC6 = sheet ADC6/ADC
harness ADC7 = port ADC7 = sheet ADC7/ADC
harness ADC8 = port ADC8 = sheet ADC8/ADC
harness ANALOG1 = port ANALOG1
harness ANALOG2 = port ANALOG2
harness ANALOG3 = port ANALOG3
harness ANALOG4 = port ANALOG4

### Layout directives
differential pair: ACLK.OSCCLKA_N, ACLK.OSCCLKA_P

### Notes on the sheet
- Power Usage (504mW)
  OP284FS 20mA * 5V = 100mW
  LTC6655 7.5mA * 15V = 112mW
  Si53365-B-GT 150mA * 1.8V = 270mW
  SN65LVDT2 8mA * 3.3V = 22mW
- Voltage Legend:
  SW+2V5 = 2.5V from switcher
  SW+6V = 6V from switcher
  ADC Power
  AVDD1V8 = 1.8V ADC apwr
  DVDD1V8 = 1.8V ADC dpwr
  AVDD5V0 = 5V ADC apwr
  DVDD5V0 = 5V ADC dpwr
  Phase Power:
  DVDD5V0 = > P1_5V0
  DVDD5V0 = > P2_5V0
  FPGA Power:
  AVCC1V8 = XADCVCC
  VCC3V3 = VCC
  VCC2V5 = FPGA 2.5V dpwr LVDS Power
  VCC1V8 = VDD = VCCAUX
  VCC1V0 = VCCINT = VCCBRAM
  PCIe
  AVTT = 1.2V
  AVCC = 1.0V
- LTC6655LN LS8 Package
  Dropout Voltage 500mV
  Separate VOUTS/NR from VOUTF?  Maybe
  place a zero ohm resistor for optional part deployment.

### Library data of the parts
C1 = ChipCap: C2220 22u Ruby; Part Number: 16MU226MD35750
C2 C165 C177 C262 C512 = ChipCap: C0805 100n; Part Number: KGM21NR71H104KM
C7 C8 = ChipCap: C1210 10u; Part Number: CL32B106KAULNNE
D1 D2 = DIODE: Single diode; Part Number: BAS16D-E3-08
D3 = DIODE_ZENER: Single zener diode 12V; Part Number: BZT52C12-13-F
LOGO?#1 = LIGO_logo
R1 = ChipRes1: R0603 10k; Part Number: ERA-3ARB103V
R2 R8 R665 R666 = ChipRes1: R0603 100; Part Number: ERA-3AEB101V
R3 = ChipRes1: R0603 680; Part Number: RG1608P-681-B-T5
R132 = ChipRes1: R0402 100; Part Number: TNPW0402100RBEED
U1 = CMP-09137-000088-1: IC VREF SERIES 0.025% 8CLCC
U42 = SN65LVDT2DBV: Single LVDS Receiver with 100 Ohm termination; Part Number: 296-6896-1-ND
U100 = CMP-0510-00563-1: 1:8 Low Jitter CMOS Clock Buffer, 1 to 200 MHz, -40 to 85 degC, 16-pin SOP
U133 = OP284FS: Precision Rail-to-Rail Input and Output Operational Amplifier; Part Number: OP284FSZ-REEL7

## Sheet AD32_Conv.SchDoc: Converter Prototype ADC
size B; Engineer: Daniel Sigg; SheetNumber: 5; SheetTotal: 17
Used 8 times, as channels Analog/ADC1, Analog/ADC2, Analog/ADC3, Analog/ADC4, Analog/ADC5, Analog/ADC6, Analog/ADC7, Analog/ADC8. Parts and nets are listed once, with the designators drawn on the sheet.
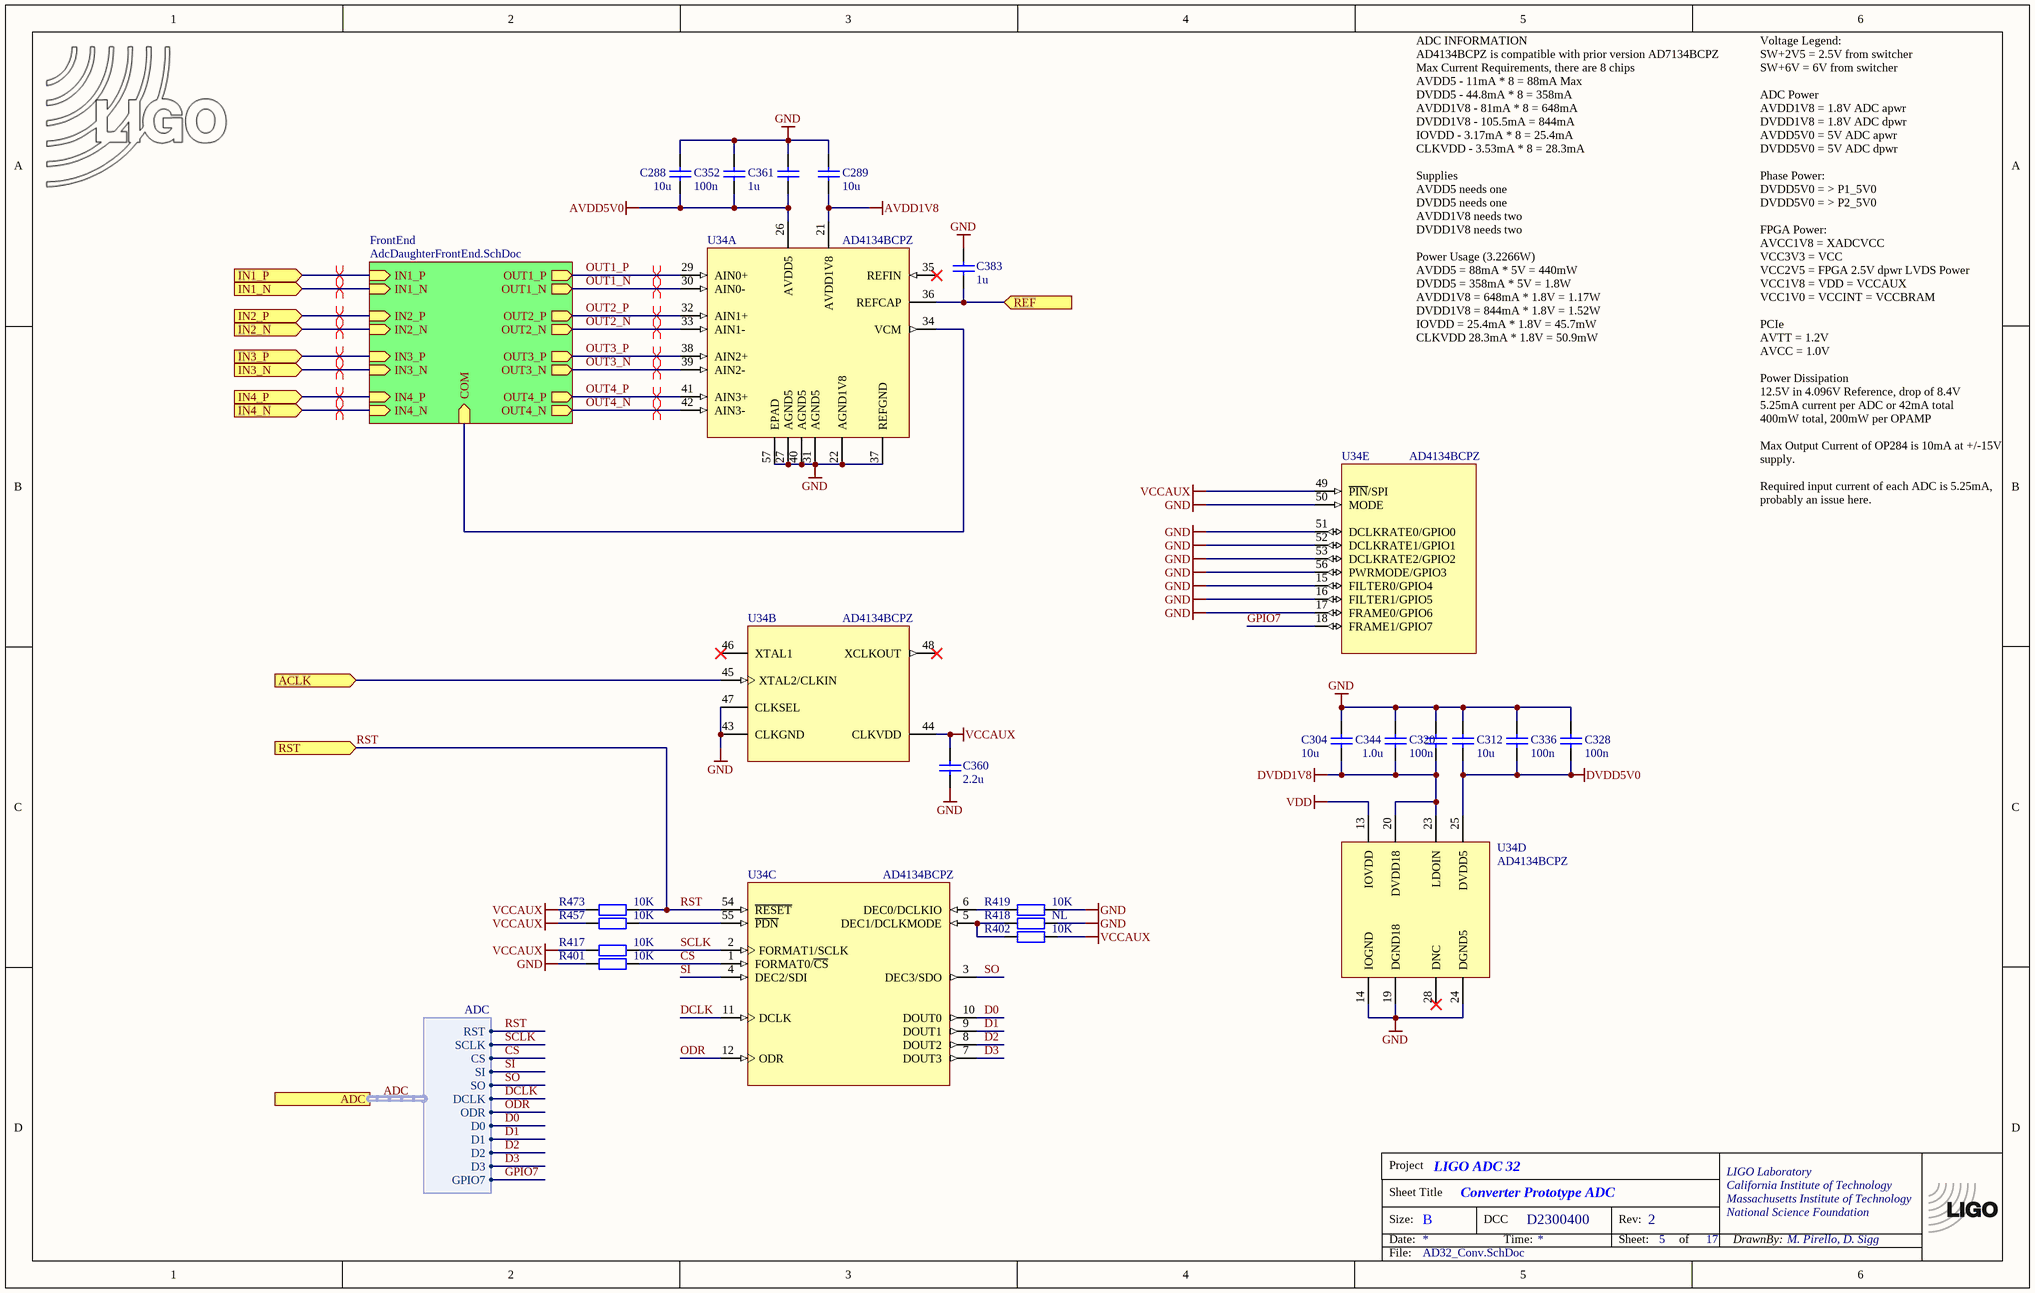
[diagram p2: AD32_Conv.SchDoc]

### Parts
*?  TitleBlock  (value not drawn)  (graphical)
C288  10u  [CC1005-0402]
C289  10u  [CC1005-0402]
C304  10u  [CC1005-0402]
C312  10u  [CC1005-0402]
C320  100n  [CC0603-0201]
C328  100n  [CC0603-0201]
C336  100n  [CC0603-0201]
C344  1.0u  [CC1005-0402]
C352  100n  [CC0603-0201]
C360  2.2u  [CC0603-0201]
C361  value 1u  [CC0603-0201]  (hidden comment: 1.0u)
C383  value 1u  [CC0603-0201]  (hidden comment: 1.0u)
LOGO?  LIGO logo  [LIGO_LOGO]  (value not drawn)  (graphical)
R401  10K  [CR0603-0201]
R402  10K  [CR0603-0201]
R417  10K  [CR0603-0201]
R418  NL  [CR0603-0201]
R419  10K  [CR0603-0201]
R457  10K  [CR0603-0201]
R473  10K  [CR0603-0201]
U34  AD4134BCPZ  [CP-56-9_ADI]  (parts A,B,C,D,E of 5)

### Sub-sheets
FrontEnd = AdcDaughterFrontEnd.SchDoc: IN1_P (in), IN1_N (in), OUT1_P (out), OUT1_N (out), IN2_P (in), IN2_N (in), OUT2_P (out), OUT2_N (out), IN3_P (in), IN3_N (in), OUT3_P (out), OUT3_N (out), IN4_P (in), IN4_N (in), OUT4_P (out), OUT4_N (out), COM (in)

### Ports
ACLK (in), ADC (harness ADC), IN1_N (in), IN1_P (in), IN2_N (in), IN2_P (in), IN3_N (in), IN3_P (in), IN4_N (in), IN4_P (in), REF (in), RST (in)

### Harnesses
ADC: RST, SCLK, CS, SI, SO, DCLK, ODR, D0, D1, D2, D3, GPIO7

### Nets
AVDD1V8: C289.1 U34.21(AVDD1V8)
AVDD5V0: C288.1 C352.1 C361.1 U34.26(AVDD5)
DVDD1V8: C304.1 C320.1 C344.1 U34.20(DVDD18) U34.23(LDOIN)
DVDD5V0: C312.1 C328.1 C336.1 U34.25(DVDD5)
GND: C288.2 C289.2 C304.2 C312.2 C320.2 C328.2 C336.2 C344.2 C352.2 C360.2 C361.2 C383.1 R401.2 R418.1 R419.1 U34.14(IOGND) U34.15(FILTER0/GPIO4) U34.16(FILTER1/GPIO5) U34.17(FRAME0/GPIO6) U34.19(DGND18) U34.22(AGND1V8) U34.24(DGND5) U34.27(AGND5) U34.31(AGND5) U34.37(REFGND) U34.40(AGND5) U34.43(CLKGND) U34.47(CLKSEL) U34.50(MODE) U34.51(DCLKRATE0/GPIO0) U34.52(DCLKRATE1/GPIO1) U34.53(DCLKRATE2/GPIO2) U34.56(PWRMODE/GPIO3) U34.57(EPAD)
VCCAUX: C360.1 R402.1 R417.2 R457.2 R473.2 U34.44(CLKVDD) U34.49(~{PIN}/SPI)
VDD: U34.13(IOVDD)
ACLK: U34.45(XTAL2/CLKIN) ; port ACLK
CS: R401.1 U34.1(FORMAT0/~{CS}) ; port ADC.CS  [project net ADC.CS]
D0: U34.10(DOUT0) ; port ADC.D0  [project net ADC.D0]
D1: U34.9(DOUT1) ; port ADC.D1  [project net ADC.D1]
D2: U34.8(DOUT2) ; port ADC.D2  [project net ADC.D2]
D3: U34.7(DOUT3) ; port ADC.D3  [project net ADC.D3]
DCLK: U34.11(DCLK) ; port ADC.DCLK  [project net ADC.DCLK]
GPIO7: U34.18(FRAME1/GPIO7) ; port ADC.GPIO7  [project net ADC.GPIO7]
IN1_N: port IN1_N, sheet FrontEnd/IN1_N
IN1_P: port IN1_P, sheet FrontEnd/IN1_P
IN2_N: port IN2_N, sheet FrontEnd/IN2_N
IN2_P: port IN2_P, sheet FrontEnd/IN2_P
IN3_N: port IN3_N, sheet FrontEnd/IN3_N
IN3_P: port IN3_P, sheet FrontEnd/IN3_P
IN4_N: port IN4_N, sheet FrontEnd/IN4_N
IN4_P: port IN4_P, sheet FrontEnd/IN4_P
ODR: U34.12(ODR) ; port ADC.ODR  [project net ADC.ODR]
OUT1_N: U34.30(AIN0-) ; sheet FrontEnd/OUT1_N
OUT1_P: U34.29(AIN0+) ; sheet FrontEnd/OUT1_P
OUT2_N: U34.33(AIN1-) ; sheet FrontEnd/OUT2_N
OUT2_P: U34.32(AIN1+) ; sheet FrontEnd/OUT2_P
OUT3_N: U34.39(AIN2-) ; sheet FrontEnd/OUT3_N
OUT3_P: U34.38(AIN2+) ; sheet FrontEnd/OUT3_P
OUT4_N: U34.42(AIN3-) ; sheet FrontEnd/OUT4_N
OUT4_P: U34.41(AIN3+) ; sheet FrontEnd/OUT4_P
REF: C383.2 U34.36(REFCAP) ; port REF
RST: R473.1 U34.54(~{RESET}) ; port RST, port ADC.RST  [project net ADC.RST]
SCLK: R417.1 U34.2(FORMAT1/SCLK) ; port ADC.SCLK  [project net ADC.SCLK]
SI: U34.4(DEC2/SDI) ; port ADC.SI  [project net ADC.SI]
SO: U34.3(DEC3/SDO) ; port ADC.SO  [project net ADC.SO]
NetR402_2: R402.2 R418.2 U34.5(DEC1/DCLKMODE)
NetR419_2: R419.2 U34.6(DEC0/DCLKIO)
NetR457_1: R457.1 U34.55(~{PDN})
NetU34_34: U34.34(VCM) ; sheet FrontEnd/COM

Not connected (* = marked no-connect by the designer): U34 28(DNC)* 35(REFIN)* 46(XTAL1)* 48(XCLKOUT)*

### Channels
Analog/ADC1: designators *?=*?A#1 C288=C288A C289=C289A C304=C304A C312=C312A C320=C320A C328=C328A C336=C336A C344=C344A C352=C352A C360=C360A C361=C361A C383=C383A LOGO?=LOGO?A#1 R401=R401A R402=R402A R417=R417A R418=R418A R419=R419A R457=R457A R473=R473A U34=U34A; ports ACLK=ACLK1 IN1_N=ANALOG1.A1_N IN1_P=ANALOG1.A1_P IN2_N=ANALOG1.A2_N IN2_P=ANALOG1.A2_P IN3_N=ANALOG1.A3_N IN3_P=ANALOG1.A3_P IN4_N=ANALOG1.A4_N IN4_P=ANALOG1.A4_P REF=REF0 RST=ADC.RST
Analog/ADC2: designators *?=*?B#1 C288=C288B C289=C289B C304=C304B C312=C312B C320=C320B C328=C328B C336=C336B C344=C344B C352=C352B C360=C360B C361=C361B C383=C383B LOGO?=LOGO?B#1 R401=R401B R402=R402B R417=R417B R418=R418B R419=R419B R457=R457B R473=R473B U34=U34B; ports ACLK=ACLK2 IN1_N=ANALOG1.A5_N IN1_P=ANALOG1.A5_P IN2_N=ANALOG1.A6_N IN2_P=ANALOG1.A6_P IN3_N=ANALOG1.A7_N IN3_P=ANALOG1.A7_P IN4_N=ANALOG1.A8_N IN4_P=ANALOG1.A8_P REF=REF0 RST=ADC.RST
Analog/ADC3: designators *?=*?C#1 C288=C288C C289=C289C C304=C304C C312=C312C C320=C320C C328=C328C C336=C336C C344=C344C C352=C352C C360=C360C C361=C361C C383=C383C LOGO?=LOGO?C#1 R401=R401C R402=R402C R417=R417C R418=R418C R419=R419C R457=R457C R473=R473C U34=U34C; ports ACLK=ACLK3 IN1_N=ANALOG2.A1_N IN1_P=ANALOG2.A1_P IN2_N=ANALOG2.A2_N IN2_P=ANALOG2.A2_P IN3_N=ANALOG2.A3_N IN3_P=ANALOG2.A3_P IN4_N=ANALOG2.A4_N IN4_P=ANALOG2.A4_P REF=REF0 RST=ADC.RST
Analog/ADC4: designators *?=*?D#1 C288=C288D C289=C289D C304=C304D C312=C312D C320=C320D C328=C328D C336=C336D C344=C344D C352=C352D C360=C360D C361=C361D C383=C383D LOGO?=LOGO?D#1 R401=R401D R402=R402D R417=R417D R418=R418D R419=R419D R457=R457D R473=R473D U34=U34D; ports ACLK=ACLK4 IN1_N=ANALOG2.A5_N IN1_P=ANALOG2.A5_P IN2_N=ANALOG2.A6_N IN2_P=ANALOG2.A6_P IN3_N=ANALOG2.A7_N IN3_P=ANALOG2.A7_P IN4_N=ANALOG2.A8_N IN4_P=ANALOG2.A8_P REF=REF0 RST=ADC.RST
Analog/ADC5: designators *?=*?E#1 C288=C288E C289=C289E C304=C304E C312=C312E C320=C320E C328=C328E C336=C336E C344=C344E C352=C352E C360=C360E C361=C361E C383=C383E LOGO?=LOGO?E#1 R401=R401E R402=R402E R417=R417E R418=R418E R419=R419E R457=R457E R473=R473E U34=U34E; ports ACLK=ACLK5 IN1_N=ANALOG3.A1_N IN1_P=ANALOG3.A1_P IN2_N=ANALOG3.A2_N IN2_P=ANALOG3.A2_P IN3_N=ANALOG3.A3_N IN3_P=ANALOG3.A3_P IN4_N=ANALOG3.A4_N IN4_P=ANALOG3.A4_P REF=REF1 RST=ADC.RST
Analog/ADC6: designators *?=*?F#1 C288=C288F C289=C289F C304=C304F C312=C312F C320=C320F C328=C328F C336=C336F C344=C344F C352=C352F C360=C360F C361=C361F C383=C383F LOGO?=LOGO?F#1 R401=R401F R402=R402F R417=R417F R418=R418F R419=R419F R457=R457F R473=R473F U34=U34F; ports ACLK=ACLK6 IN1_N=ANALOG3.A5_N IN1_P=ANALOG3.A5_P IN2_N=ANALOG3.A6_N IN2_P=ANALOG3.A6_P IN3_N=ANALOG3.A7_N IN3_P=ANALOG3.A7_P IN4_N=ANALOG3.A8_N IN4_P=ANALOG3.A8_P REF=REF1 RST=ADC.RST
Analog/ADC7: designators *?=*?G#1 C288=C288G C289=C289G C304=C304G C312=C312G C320=C320G C328=C328G C336=C336G C344=C344G C352=C352G C360=C360G C361=C361G C383=C383G LOGO?=LOGO?G#1 R401=R401G R402=R402G R417=R417G R418=R418G R419=R419G R457=R457G R473=R473G U34=U34G; ports ACLK=ACLK7 IN1_N=ANALOG4.A1_N IN1_P=ANALOG4.A1_P IN2_N=ANALOG4.A2_N IN2_P=ANALOG4.A2_P IN3_N=ANALOG4.A3_N IN3_P=ANALOG4.A3_P IN4_N=ANALOG4.A4_N IN4_P=ANALOG4.A4_P REF=REF1 RST=ADC.RST
Analog/ADC8: designators *?=*?H#1 C288=C288H C289=C289H C304=C304H C312=C312H C320=C320H C328=C328H C336=C336H C344=C344H C352=C352H C360=C360H C361=C361H C383=C383H LOGO?=LOGO?H#1 R401=R401H R402=R402H R417=R417H R418=R418H R419=R419H R457=R457H R473=R473H U34=U34H; ports ACLK=ACLK8 IN1_N=ANALOG4.A5_N IN1_P=ANALOG4.A5_P IN2_N=ANALOG4.A6_N IN2_P=ANALOG4.A6_P IN3_N=ANALOG4.A7_N IN3_P=ANALOG4.A7_P IN4_N=ANALOG4.A8_N IN4_P=ANALOG4.A8_P REF=REF1 RST=ADC.RST

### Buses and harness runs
harness ADC = port ADC

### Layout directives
differential pair: ANALOG1.A1_N, ANALOG1.A1_P, ANALOG1.A2_N, ANALOG1.A2_P, ANALOG1.A3_N, ANALOG1.A3_P, ANALOG1.A4_N, ANALOG1.A4_P, OUT1_N_ADC1, OUT1_P_ADC1, OUT2_N_ADC1, OUT2_P_ADC1, OUT3_N_ADC1, OUT3_P_ADC1, OUT4_N_ADC1, OUT4_P_ADC1

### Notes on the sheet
- ADC INFORMATION
  AD4134BCPZ is compatible with prior version AD7134BCPZ
  Max Current Requirements, there are 8 chips
  AVDD5 - 11mA * 8 = 88mA Max
  DVDD5 - 44.8mA * 8 = 358mA
  AVDD1V8 - 81mA * 8 = 648mA
  DVDD1V8 - 105.5mA = 844mA
  IOVDD - 3.17mA * 8 = 25.4mA
  CLKVDD - 3.53mA * 8 = 28.3mA
  Supplies
  AVDD5 needs one
  DVDD5 needs one
  AVDD1V8 needs two
  DVDD1V8 needs two
  Power Usage (3.2266W)
  AVDD5 = 88mA * 5V = 440mW
  DVDD5 = 358mA * 5V = 1.8W
  AVDD1V8 = 648mA * 1.8V = 1.17W
  DVDD1V8 = 844mA * 1.8V = 1.52W
  IOVDD = 25.4mA * 1.8V = 45.7mW
  CLKVDD 28.3mA * 1.8V = 50.9mW
- Voltage Legend:
  SW+2V5 = 2.5V from switcher
  SW+6V = 6V from switcher
  ADC Power
  AVDD1V8 = 1.8V ADC apwr
  DVDD1V8 = 1.8V ADC dpwr
  AVDD5V0 = 5V ADC apwr
  DVDD5V0 = 5V ADC dpwr
  Phase Power:
  DVDD5V0 = > P1_5V0
  DVDD5V0 = > P2_5V0
  FPGA Power:
  AVCC1V8 = XADCVCC
  VCC3V3 = VCC
  VCC2V5 = FPGA 2.5V dpwr LVDS Power
  VCC1V8 = VDD = VCCAUX
  VCC1V0 = VCCINT = VCCBRAM
  PCIe
  AVTT = 1.2V
  AVCC = 1.0V
  Power Dissipation
  12.5V in 4.096V Reference, drop of 8.4V
  5.25mA current per ADC or 42mA total
  400mW total, 200mW per OPAMP
  Max Output Current of OP284 is 10mA at +/-15V supply.
  Required input current of each ADC is 5.25mA, probably an issue here.

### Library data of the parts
C288 C289 C304 C312 = ChipCap: C0402 10u; Part Number: CC0402MRX5R6BB106
C320 C328 C336 C352 = ChipCap: C0201 100n; Part Number: GRM033Z71C104KE14D
C344 = ChipCap: C0402 1.0u; Part Number: C0402C105K4PACTU
C360 = ChipCap: C0201 2.2u; Part Number: GRM033R61A225KE47D
C361 C383 = ChipCap: C0201 1.0u; Part Number: CL03A105KP3NSNC
LOGO? = LIGO_logo
R401 R417 R419 R457 R473 = ChipRes1: R0201 10k; Part Number: ERA-1AEB103C
R402 = ChipRes1: R0201 10K; Part Number: ERA-1AEB103C
R418 = ChipRes1: R0201 NL
U34 = AD7134: 24-Bit, 4-Channel Simultaneous Sampling 1.5 MSPS Precision Alias Free ADC; Part Number: 505-AD4134BCPZ-ND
